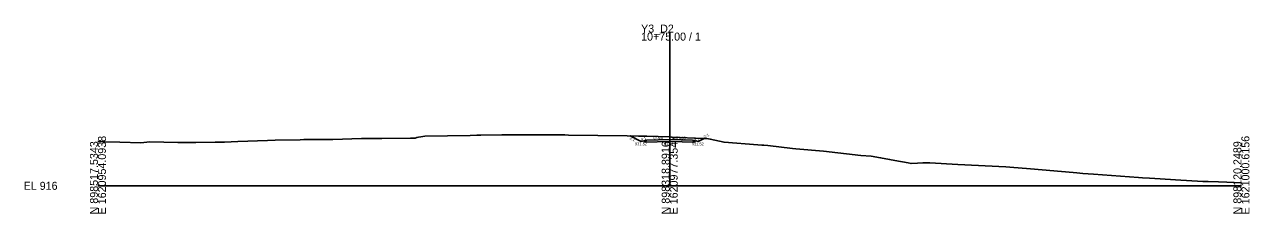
# Model space of a CAD drawing. Extents: x 162 to 3869, y 3 to 5514.
# Drawn here: x 3440.3 to 3868.9, y 2369.4 to 2435.6 of the extents above; entities that cross this region are included whole.
import ezdxf

# ---------------------------------------------------------------- set-up
doc = ezdxf.new("R2010")
doc.units = 0
for name, color, linetype in [('Exist Cross Section Cell', 7, 'Continuous'), ('Exist XS Center Line Elevation Label', 7, 'Continuous'), ('Exist XS Ground Line', 7, 'Continuous'), ('Old_Level_1', 7, 'Continuous'), ('Prop CMT Pvmt Gravel', 7, 'Continuous'), ('Prop CMT Slope Grass', 7, 'Continuous'), ('Prop CMT Subgrade Earthwork', 7, 'Continuous'), ('Prop XS Earthwork Shape', 7, 'Continuous'), ('Prop XS SE Text', 7, 'Continuous'), ('Prop XS Side Slope Text', 7, 'Continuous')]:
    doc.layers.add(name, color=color, linetype=linetype)

msp = doc.modelspace()

# ---------------------------------------------------------------- linework, layer by layer
at = {"layer": 'Exist Cross Section Cell'}
for p, q in [((3666.03, 2379.08), (3666.03, 2432.72)), ((3466.03, 2379.08), (3666.03, 2379.08)), ((3666.03, 2379.08), (3866.03, 2379.08))]:
    msp.add_line(p, q, dxfattribs=at)
at = {"layer": 'Exist XS Ground Line'}
msp.add_lwpolyline([(3466.03, 2394.6), (3468.38, 2394.51), (3473.7, 2394.36), (3481.07, 2394.16), (3484.17, 2394.43), (3494.01, 2394.2), (3500.24, 2394.27), (3506.98, 2394.33), (3510.27, 2394.42), (3515, 2394.6), (3525.35, 2394.92), (3527.98, 2395.05), (3536.75, 2395.2), (3538.05, 2395.24), (3548.15, 2395.27), (3558.18, 2395.61), (3561.06, 2395.65), (3565.31, 2395.67), (3575.36, 2395.73), (3577.04, 2395.75), (3577.6, 2395.94), (3578.2, 2396.11), (3579.01, 2396.24), (3580.4, 2396.42), (3596.27, 2396.73), (3598.56, 2396.78), (3600.01, 2396.8), (3607.32, 2396.9), (3611.18, 2396.92), (3618.6, 2396.96), (3627.98, 2396.9), (3628.87, 2396.89), (3629.39, 2396.88), (3630.58, 2396.86), (3651.15, 2396.53), (3655.12, 2396.52), (3658.04, 2396.46), (3666.03, 2396.18), (3666.86, 2396.15), (3677.56, 2395.7), (3678.98, 2395.59), (3680.25, 2395.43), (3685.04, 2394.33), (3696.86, 2393.4), (3698.21, 2393.36), (3699.01, 2393.31), (3700.35, 2393.14), (3709.02, 2392.12), (3710.13, 2391.99), (3719.8, 2391.2), (3732.93, 2389.72), (3736.48, 2389.43), (3739.81, 2388.93), (3742.97, 2388.33), (3744.74, 2387.95), (3749.46, 2387.12), (3750.48, 2386.88), (3752.74, 2387.03), (3754.61, 2387.15), (3757.05, 2387.14), (3766.79, 2386.53), (3783.66, 2385.77), (3785.03, 2385.63), (3792.29, 2385.04), (3807.2, 2383.72), (3808.48, 2383.59), (3810.6, 2383.4), (3814.35, 2383.12), (3830.07, 2381.98), (3831.39, 2381.9), (3833.89, 2381.74), (3837.67, 2381.51), (3843.03, 2381.22), (3852.53, 2380.65), (3854.35, 2380.55), (3857.99, 2380.43), (3860.97, 2380.31), (3866.03, 2380.15)], dxfattribs=at)
at = {"layer": 'Old_Level_1'}
for p, q in [((3656.94, 2394.82), (3658.03, 2395.09)), ((3675.11, 2394.82), (3674.03, 2395.09))]:
    msp.add_line(p, q, dxfattribs=at)
at = {"layer": 'Prop CMT Pvmt Gravel'}
for points in [[(3658.03, 2395.09), (3657.34, 2394.41)], [(3666.03, 2395.25), (3658.03, 2395.09)], [(3666.03, 2395.25), (3674.03, 2395.09)], [(3674.03, 2395.09), (3674.71, 2394.41)]]:
    msp.add_lwpolyline(points, dxfattribs=at)
at = {"layer": 'Prop CMT Slope Grass'}
for p, q in [((3652.16, 2396.53), (3656.03, 2394.59)), ((3678.15, 2395.65), (3676.03, 2394.59)), ((3656.03, 2394.59), (3656.94, 2394.82)), ((3676.03, 2394.59), (3675.11, 2394.82))]:
    msp.add_line(p, q, dxfattribs=at)
at = {"layer": 'Prop CMT Subgrade Earthwork'}
for p, q in [((3656.94, 2394.82), (3657.34, 2394.41)), ((3666.03, 2394.59), (3657.34, 2394.41)), ((3666.03, 2394.59), (3674.71, 2394.41)), ((3675.11, 2394.82), (3674.71, 2394.41))]:
    msp.add_line(p, q, dxfattribs=at)
at = {"layer": 'Prop XS Earthwork Shape'}
for points in [[(3678.15, 2395.65), (3676.03, 2394.59), (3675.11, 2394.82), (3674.71, 2394.41), (3666.03, 2394.59), (3657.34, 2394.41), (3656.94, 2394.82), (3656.03, 2394.59), (3652.16, 2396.53), (3655.12, 2396.52), (3658.04, 2396.46), (3666.03, 2396.18), (3666.86, 2396.15), (3677.56, 2395.7)], [(3652.16, 2396.53), (3655.12, 2396.52), (3658.04, 2396.46), (3666.03, 2396.18), (3666.86, 2396.15), (3677.56, 2395.7), (3678.15, 2395.65), (3676.03, 2394.59), (3675.11, 2394.82), (3674.71, 2394.41), (3666.03, 2394.59), (3657.34, 2394.41), (3656.94, 2394.82), (3656.03, 2394.59)]]:
    msp.add_lwpolyline(points, close=True, dxfattribs=at)

# ---------------------------------------------------------------- texts
at = {"layer": 'Exist Cross Section Cell'}
for s, p in [('Y3_D2', (3656.03, 2432.72)), ('10+75.00 / 1', (3656.03, 2429.92)), ('EL 916', (3440.03, 2377.68))]:
    msp.add_text(s, height=2.8, dxfattribs=at).set_placement(p)
for s, p in [('E 1620954.0938', (3468.83, 2369.08)), ('E 1620977.3547', (3668.83, 2369.08)), ('E 1621000.6156', (3868.83, 2369.08)), ('N 898517.5343', (3466.03, 2369.08)), ('N 898318.8916', (3666.03, 2369.08)), ('N 898120.2489', (3866.03, 2369.08))]:
    msp.add_text(s, height=2.8, rotation=90, dxfattribs=at).set_placement(p)
at = {"layer": 'Exist XS Center Line Elevation Label'}
msp.add_text('933.10', height=1, dxfattribs=at).set_placement((3664, 2393.2))
at = {"layer": 'Prop XS SE Text'}
for rotation, p in [(1.1458, (3660.27, 2395.39)), (358.8542, (3668.19, 2395.37))]:
    msp.add_text('0.020', height=1, rotation=rotation, dxfattribs=at).set_placement(p)
at = {"layer": 'Prop XS Side Slope Text'}
for s, rotation, p in [('2:1', 333.4349, (3651.96, 2395.47)), ('4:1', 14.7964, (3656.07, 2394.76)), ('4:1', 345.2036, (3674.4, 2395.19)), ('2:1', 26.5651, (3678.22, 2395.72))]:
    msp.add_text(s, height=1, rotation=rotation, dxfattribs=at).set_placement(p)
for p in [(3653.87, 2393.28), (3673.77, 2393.22)]:
    msp.add_text('931.52', height=1, dxfattribs=at).set_placement(p)

doc.saveas('drawing.dxf')
